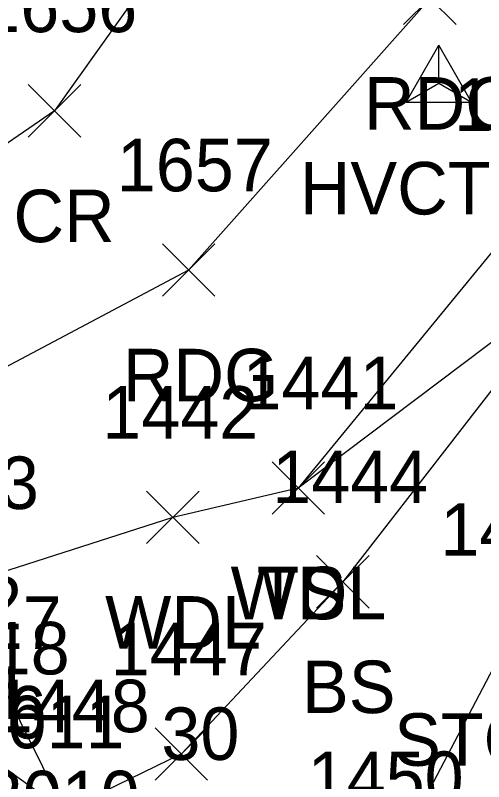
# Model space of a CAD drawing. Extents: x 1512665 to 1513714, y 110636 to 112816.
# Drawn here: x 1513104.22 to 1513122.08, y 110778.54 to 110807.73 of the extents above; entities that cross this region are included whole.
import ezdxf

# ---------------------------------------------------------------- set-up
doc = ezdxf.new("R2010")
doc.units = 0
for name, color, linetype in [('C_A', 7, 'Continuous'), ('C_I', 7, 'Continuous'), ('CPSM', 7, 'Continuous'), ('L_A', 7, 'Continuous'), ('L_I', 7, 'Continuous'), ('L_TIC', 7, 'Continuous'), ('LARO', 7, 'Continuous'), ('LASF', 7, 'Continuous'), ('LAWA', 7, 'Continuous'), ('LELB', 7, 'Continuous'), ('P_A', 7, 'Continuous'), ('P_I', 7, 'Continuous'), ('P_TIC', 7, 'Continuous'), ('PEU', 7, 'Continuous'), ('PRC', 7, 'Continuous')]:
    doc.layers.add(name, color=color, linetype=linetype)

msp = doc.modelspace()

# ---------------------------------------------------------------- linework, layer by layer
at = {"layer": 'CPSM'}
for p, q in [((1513119.124, 110804.425), (1513120.374, 110806.59)), ((1513119.124, 110804.425), (1513120.374, 110806.59)), ((1513119.124, 110804.425), (1513120.374, 110806.59)), ((1513119.124, 110804.425), (1513120.374, 110806.59)), ((1513121.624, 110804.425), (1513120.374, 110806.59)), ((1513120.374, 110805.146), (1513120.374, 110806.59)), ((1513121.624, 110804.425), (1513120.374, 110806.59)), ((1513120.374, 110805.146), (1513120.374, 110806.59)), ((1513121.624, 110804.425), (1513120.374, 110806.59)), ((1513120.374, 110805.146), (1513120.374, 110806.59)), ((1513121.624, 110804.425), (1513120.374, 110806.59)), ((1513120.374, 110805.146), (1513120.374, 110806.59)), ((1513119.124, 110804.425), (1513120.374, 110805.146)), ((1513119.124, 110804.425), (1513120.374, 110805.146)), ((1513119.124, 110804.425), (1513120.374, 110805.146)), ((1513119.124, 110804.425), (1513120.374, 110805.146)), ((1513120.374, 110805.146), (1513120.374, 110805.146)), ((1513120.374, 110805.146), (1513121.624, 110804.425)), ((1513120.374, 110805.146), (1513120.374, 110805.146)), ((1513120.374, 110805.146), (1513121.624, 110804.425)), ((1513120.374, 110805.146), (1513120.374, 110805.146)), ((1513120.374, 110805.146), (1513121.624, 110804.425)), ((1513120.374, 110805.146), (1513120.374, 110805.146)), ((1513120.374, 110805.146), (1513121.624, 110804.425)), ((1513119.124, 110804.425), (1513121.624, 110804.425)), ((1513119.124, 110804.425), (1513121.624, 110804.425)), ((1513119.124, 110804.425), (1513121.624, 110804.425)), ((1513119.124, 110804.425), (1513121.624, 110804.425))]:
    msp.add_line(p, q, dxfattribs=at)
at = {"layer": 'L_TIC'}
for points in [[(1513114.011, 110788.722), (1513116.011, 110790.722)], [(1513116.011, 110788.722), (1513114.011, 110790.722)], [(1513114.011, 110788.722), (1513116.011, 110790.722)], [(1513116.011, 110788.722), (1513114.011, 110790.722)], [(1513109.226, 110787.604), (1513111.226, 110789.604)], [(1513111.226, 110787.604), (1513109.226, 110789.604)], [(1513115.71, 110785.148), (1513117.71, 110787.148)], [(1513117.71, 110785.148), (1513115.71, 110787.148)], [(1513109.55, 110778.591), (1513111.55, 110780.591)], [(1513111.55, 110778.591), (1513109.55, 110780.591)]]:
    msp.add_lwpolyline(points, dxfattribs=at)
at = {"layer": 'LARO'}
msp.add_lwpolyline([(1513103.034, 110779.623), (1513106.089, 110777.421)], dxfattribs=at)
at = {"layer": 'LASF'}
msp.add_lwpolyline([(1513155.27, 110725.127), (1513152.549, 110754.364), (1513148, 110771.81), (1513152.248, 110792.504), (1513164.38, 110807.195), (1513174.006, 110832.485), (1513163.393, 110825.709), (1513157.638, 110817.684), (1513150.034, 110815.279), (1513143.722, 110818.877), (1513137.14, 110819.494), (1513132.379, 110806.573), (1513129.365, 110796.508), (1513123.124, 110784.141), (1513118.146, 110774.685), (1513122.72, 110764.726), (1513123.65, 110752.311), (1513122.832, 110742.42), (1513125.739, 110723.519), (1513127.355, 110710.167)], dxfattribs=at)
at = {"layer": 'LAWA'}
msp.add_lwpolyline([(1513169.909, 110850.574), (1513155.8, 110854.743), (1513154.003, 110849.999), (1513151.762, 110839.769), (1513150.998, 110833.435), (1513152.454, 110822.764), (1513150.034, 110815.279), (1513136.759, 110804.589), (1513129.365, 110796.508), (1513125.79, 110797.836), (1513115.011, 110789.722), (1513110.226, 110788.604), (1513101.86, 110785.924), (1513106.089, 110777.421), (1513109.383, 110771.51), (1513113.636, 110761.19), (1513120.116, 110747.897), (1513117.812, 110736.666), (1513111.118, 110720.921), (1513118.271, 110709.907)], dxfattribs=at)
at = {"layer": 'LELB'}
for points in [[(1513137.337, 110882.904), (1513136.042, 110877.657), (1513136.12, 110864.188), (1513131.893, 110853.079), (1513130.46, 110839.891), (1513131.567, 110832.675), (1513130.921, 110819.726), (1513129.422, 110808.1), (1513125.79, 110797.836), (1513116.71, 110786.148), (1513110.55, 110779.591), (1513106.089, 110777.421)], [(1513136.07, 110882.644), (1513133.23, 110875.829), (1513134.591, 110863.608), (1513129.213, 110851.444), (1513128.452, 110839.982), (1513129.607, 110832.324), (1513129.65, 110820.521), (1513127.768, 110809.822), (1513123.727, 110800.329), (1513115.011, 110789.722)]]:
    msp.add_lwpolyline(points, dxfattribs=at)
at = {"layer": 'P_TIC'}
for points in [[(1513119.028, 110807.377), (1513121.028, 110809.377)], [(1513121.028, 110807.377), (1513119.028, 110809.377)], [(1513104.713, 110803.091), (1513106.713, 110805.091)], [(1513106.713, 110803.091), (1513104.713, 110805.091)], [(1513109.828, 110797.027), (1513111.828, 110799.027)], [(1513111.828, 110797.027), (1513109.828, 110799.027)]]:
    msp.add_lwpolyline(points, dxfattribs=at)
at = {"layer": 'PEU'}
msp.add_lwpolyline([(1513170.256, 110966.545), (1513161.211, 110960.303), (1513151.369, 110951.546), (1513143.018, 110943.811), (1513133.251, 110931.043), (1513127.426, 110919.762), (1513124.626, 110897.943), (1513124.876, 110872.667), (1513125.902, 110844.176), (1513126.27, 110821.797), (1513120.028, 110808.377), (1513110.828, 110798.027), (1513092.487, 110788.311), (1513089.551, 110792.994), (1513086.517, 110797.2)], dxfattribs=at)
at = {"layer": 'PRC'}
msp.add_lwpolyline([(1513199.52, 110982.675), (1513185.86, 110980.154), (1513168.393, 110974.825), (1513156.296, 110966.817), (1513145.568, 110957.841), (1513135.79, 110952.04), (1513127.966, 110935.792), (1513122.325, 110921.104), (1513118.394, 110897.939), (1513119.913, 110872.756), (1513120.726, 110844.828), (1513118.948, 110825.045), (1513112.521, 110813.651), (1513105.713, 110804.091), (1513089.551, 110792.994)], dxfattribs=at)

# ---------------------------------------------------------------- texts
at = {"layer": 'C_A'}
msp.add_text('HVCTRL', height=2, dxfattribs=at).set_placement((1513115.067, 110800.146))
msp.add_text('HVCTRL', height=2, dxfattribs=at).set_placement((1513115.067, 110800.146))
msp.add_text('HVCTRL', height=2, dxfattribs=at).set_placement((1513115.067, 110800.146))
msp.add_text('HVCTRL', height=2, dxfattribs=at).set_placement((1513115.067, 110800.146))
at = {"layer": 'C_I'}
msp.add_text('30', height=2, dxfattribs=at).set_placement((1513109.789, 110779.364))
at = {"layer": 'L_A'}
for s, p in [('WDL', (1513112.428, 110784.722)), ('TS', (1513113.421, 110784.722)), ('WDL', (1513107.643, 110783.604)), ('BS', (1513115.151, 110781.148)), ('WDL', (1513099.278, 110780.924)), ('STONE', (1513118.667, 110779.141))]:
    msp.add_text(s, height=2, dxfattribs=at).set_placement(p)
at = {"layer": 'L_I'}
for s, p in [('1440', (1513120.947, 110803.329)), ('1441', (1513112.885, 110792.722)), ('1441', (1513112.885, 110792.722)), ('1442', (1513107.533, 110791.604)), ('1444', (1513114.017, 110789.148)), ('1443', (1513099.167, 110788.924)), ('1445', (1513120.431, 110787.141)), ('3012', (1513098.528, 110784.342)), ('2817', (1513100.034, 110783.592)), ('2818', (1513100.341, 110782.623)), ('1447', (1513107.857, 110782.591)), ('1448', (1513103.396, 110780.421)), ('1448', (1513103.396, 110780.421)), ('3096', (1513099.458, 110780.181)), ('3011', (1513102.433, 110779.808)), ('1450', (1513115.367, 110777.685)), ('3010', (1513103.009, 110776.95))]:
    msp.add_text(s, height=2, dxfattribs=at).set_placement(p)
at = {"layer": 'P_A'}
for s, p in [('RDG', (1513117.516, 110803.377)), ('CR', (1513104.146, 110799.091)), ('RDG', (1513108.316, 110793.027))]:
    msp.add_text(s, height=2, dxfattribs=at).set_placement(p)
at = {"layer": 'P_I'}
for s, p in [('1656', (1513102.917, 110807.091)), ('1657', (1513108.088, 110801.027))]:
    msp.add_text(s, height=2, dxfattribs=at).set_placement(p)

doc.saveas('drawing.dxf')
